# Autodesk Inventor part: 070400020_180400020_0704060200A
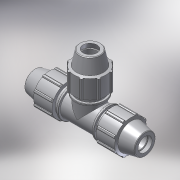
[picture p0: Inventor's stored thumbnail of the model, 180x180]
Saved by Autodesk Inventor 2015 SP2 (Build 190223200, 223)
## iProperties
Created: 2017-02
Part Number: 070400020_180400020_0704060200A
Material: PVC-Piping
Description: PLASSON TEE 20-20-20
Document SubType Name: Modeling
Designer: KIM
Mass: 92.6774 g
Surface Area: 199.44 cm^2
Volume: 66.1981 cm^3
Density: 1.4 g/cm^3
Appearance: Smooth - White
Author: KIM
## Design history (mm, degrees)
derived "07040.ipt"
feature "Solid1::07040.ipt"
tag "TaggingFeature1"
body "Solid1"
other parameters: "d4" = 6.08333, "d5" = 18.25, "d7" = 48, "d11" = 2.43333, "d13" = 120 deg, "d15" = 12 deg, "d16" = 41.76, "d18" = 1, "d19" = 35 deg, "d20" = 17.5 deg, "d21" = 44.64, "d23" = 0, "d25" = 360 deg, "d27" = 0.96, "d33" = 0.4, "d42" = 25.55, "d43" = 1.44, "d46" = 0.6, "d63" = 56, "d67" = 36, "d77" = 48, "d78" = 12 deg, "d79" = 73, "d80" = 120 deg, "d82" = 6.08333, "d85" = 36, "d86" = 41.76, "d87" = 2.43333, "d88" = 2.43333, "d89" = 18.25, "d90" = 25.55, "d96" = 7.3, "d98" = 44.64, "d99" = 35 deg, "d100" = 17.5 deg, "d102" = 0, "d103" = 0.96, "d107" = 360 deg, "d109" = 0.6, "d112" = 1, "d118" = 360 deg, "d121" = 0, "d128" = 145, "d131" = 18, "d132" = 18, "d133" = 56, "d134" = 1.12, "d135" = 7.3, "d152" = 0, "d154" = 0, "d156" = 0, "d158" = 0, "E_" = 48, "A_" = 73, "l_" = 56, "H_" = 145
